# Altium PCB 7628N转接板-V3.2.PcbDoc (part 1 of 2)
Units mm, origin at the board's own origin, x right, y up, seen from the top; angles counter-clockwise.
Board outline 53 x 34 mm, 2 copper layers (Top, Bottom), stack 1.981 mm thick; 6 components, 131 nets, 219 pads, 60 vias.
Unrouted connection lines stored in the file: 5.
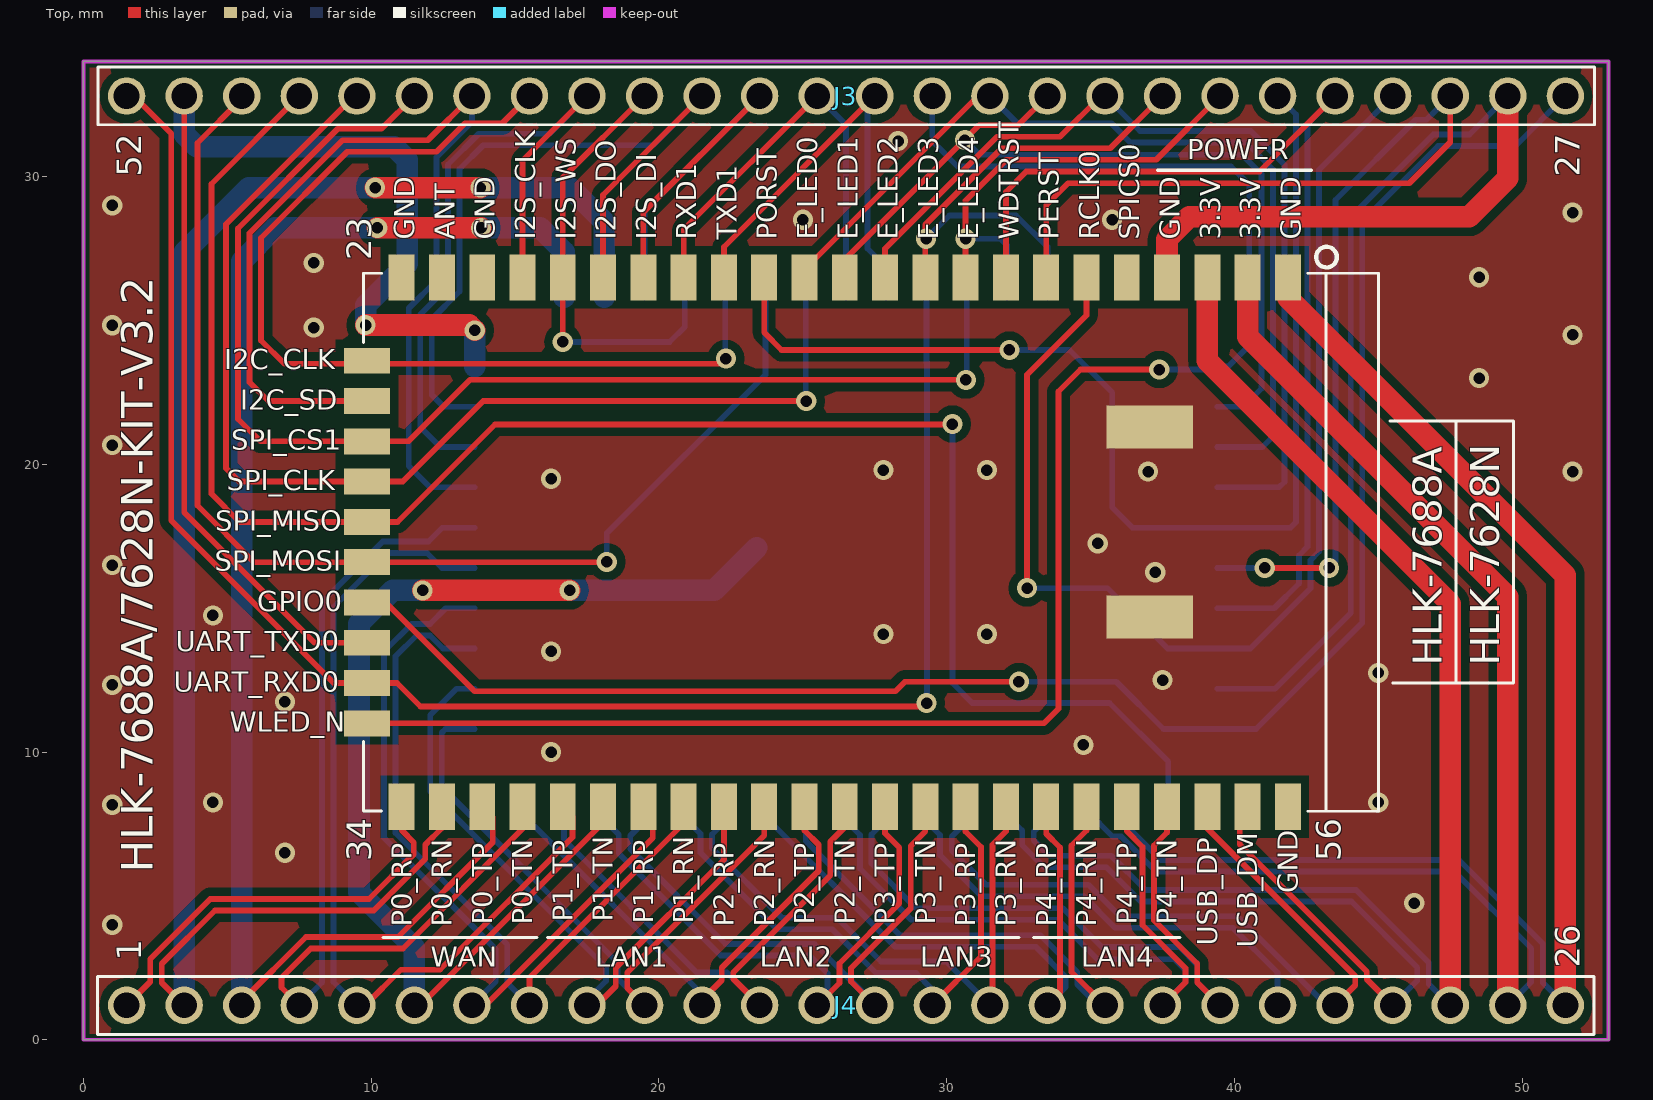
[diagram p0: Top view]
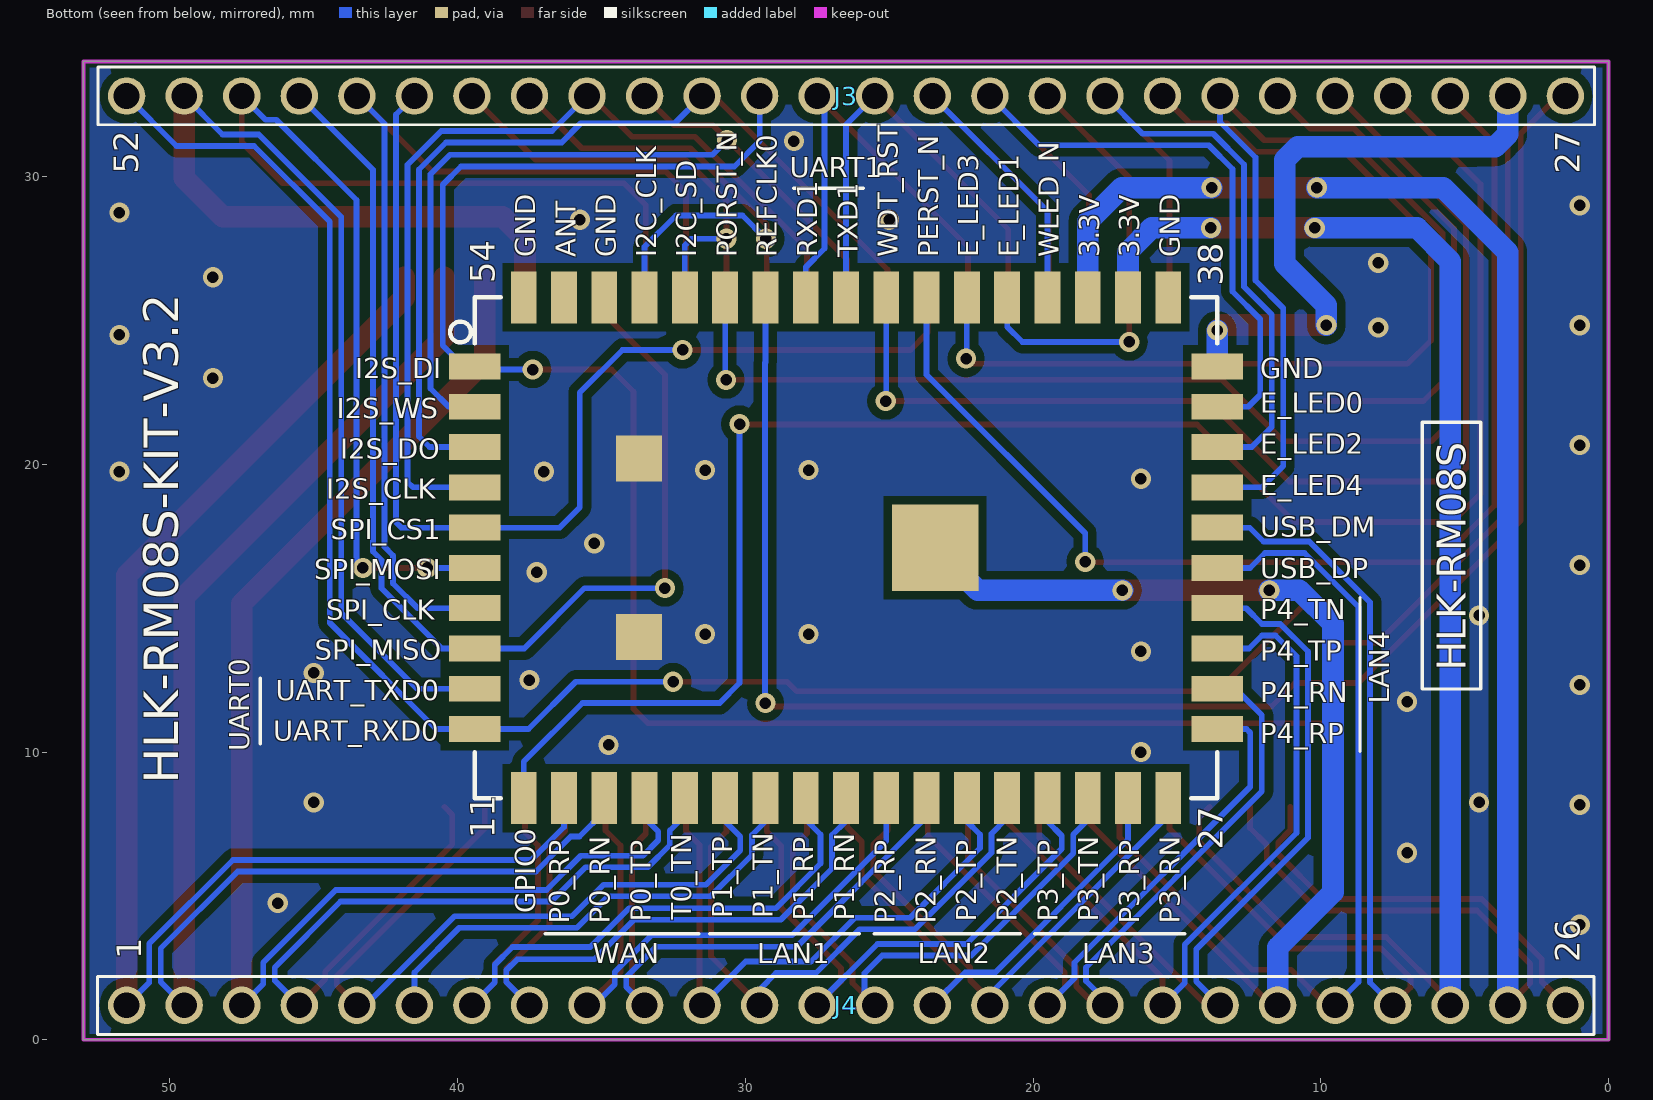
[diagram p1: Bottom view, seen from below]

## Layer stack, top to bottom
Solder Mask Top: solder mask 0.0102, Solder Resist, Dk 3.5
Top: signal copper 0.0178
Dielectric1: core 1.9456, FR-4, Dk 4.2
Bottom: signal copper 0.0178
Solder Mask Bottom: solder mask 0.0102, Solder Resist, Dk 3.5

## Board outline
0,0 53,0 53,34 0,34

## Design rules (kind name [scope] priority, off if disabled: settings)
Clearance [OnLayer('Keep-Out Layer')] p1: gap=0.15 ignorepadtopadclearanceinfootprint=FALSE
Clearance "'Net vs. Class' PADS rule_67" [All] p2: gap=0.3 ignorepadtopadclearanceinfootprint=FALSE
Clearance "'Net vs. Class' PADS rule_66" [InNet('GND') vs InNetClass('50OHM') And (IsTrack Or IsArc Or IsThruPin Or IsSMTPin Or IsVia Or IsFill Or InPolygon)] p3 off: gap=0.203 ignorepadtopadclearanceinfootprint=FALSE
Clearance "'Net vs. Class' PADS rule_64" [InNet('GND') vs InNetClass('DQ')] p4 off: gap=0.127 ignorepadtopadclearanceinfootprint=FALSE
Clearance "'Net vs. Class' PADS rule_63" [InNet('GND') And IsSMTPin vs InNetClass('DQ') And IsSMTPin] p5 off: gap=0.178 ignorepadtopadclearanceinfootprint=FALSE
Clearance "'Net vs. Class' PADS rule_62" [InNet('GND') vs InNetClass('DQ') And (IsTrack Or IsArc Or IsThruPin Or IsSMTPin Or IsVia Or IsFill Or InPolygon)] p6 off: gap=0.127 ignorepadtopadclearanceinfootprint=FALSE
Clearance "'Net vs. Class' PADS rule_60" [InNet('GND') vs InNetClass('90OHM')] p7 off: gap=0.203 ignorepadtopadclearanceinfootprint=FALSE
Clearance "'Net vs. Class' PADS rule_59" [InNet('GND') And IsSMTPin vs InNetClass('90OHM') And IsSMTPin] p8 off: gap=0.178 ignorepadtopadclearanceinfootprint=FALSE
Clearance "'Net vs. Class' PADS rule_58" [InNet('GND') vs InNetClass('90OHM') And (IsTrack Or IsArc Or IsThruPin Or IsSMTPin Or IsVia Or IsFill Or InPolygon)] p9 off: gap=0.203 ignorepadtopadclearanceinfootprint=FALSE
Clearance "'Net vs. Class' PADS rule_56" [InNet('GND') vs InNetClass('100OHM')] p10 off: gap=0.203 ignorepadtopadclearanceinfootprint=FALSE
Clearance "'Net vs. Class' PADS rule_54" [InNet('GND') vs InNetClass('100OHM') And (IsTrack Or IsArc Or IsThruPin Or IsSMTPin Or IsVia Or IsFill Or InPolygon)] p11 off: gap=0.203 ignorepadtopadclearanceinfootprint=FALSE
Clearance "'Net vs. Class' PADS rule_52" [InNet('GND') vs InNetClass('CA')] p12 off: gap=0.127 ignorepadtopadclearanceinfootprint=FALSE
Clearance "'Net vs. Class' PADS rule_51" [InNet('GND') And IsSMTPin vs InNetClass('CA') And IsSMTPin] p13 off: gap=0.178 ignorepadtopadclearanceinfootprint=FALSE
Clearance "'Net vs. Class' PADS rule_50" [InNet('GND') vs InNetClass('CA') And (IsTrack Or IsArc Or IsThruPin Or IsSMTPin Or IsVia Or IsFill Or InPolygon)] p14 off: gap=0.127 ignorepadtopadclearanceinfootprint=FALSE
Clearance "'Classon Layer' PADS rule_48" [InNetClass('DQ') And OnLayer('Top') And IsSMTPin vs IsSMTPin] p15 off: gap=0.178 ignorepadtopadclearanceinfootprint=FALSE
Clearance "'Classon Layer' PADS rule_47" [InNetClass('DQ') And OnLayer('Top') vs (IsTrack Or IsArc Or IsThruPin Or IsSMTPin Or IsVia Or IsFill Or InPolygon)] p16 off: gap=0.127 ignorepadtopadclearanceinfootprint=FALSE
Clearance "'Classon Layer' PADS rule_44" [InNetClass('CA') And OnLayer('Top') And IsSMTPin vs IsSMTPin] p17 off: gap=0.178 ignorepadtopadclearanceinfootprint=FALSE
Clearance "'Classon Layer' PADS rule_42" [InNetClass('CA') And OnLayer('Top') And (IsTrack Or IsArc) vs (IsTrack Or IsArc)] p18 off: gap=0.254 ignorepadtopadclearanceinfootprint=FALSE
Clearance "'Classon Layer' PADS rule_41" [InNetClass('CA') And OnLayer('Top') vs (IsTrack Or IsArc Or IsThruPin Or IsSMTPin Or IsVia Or IsFill Or InPolygon)] p19 off: gap=0.127 ignorepadtopadclearanceinfootprint=FALSE
Clearance "'Net' PADS rule_36" [InNetClass('Protel Created NetClass - 1') And (IsTrack Or IsArc) vs (IsTrack Or IsArc)] p20 off: gap=0.102 ignorepadtopadclearanceinfootprint=FALSE
Clearance "'Class' PADS rule_32" [InNetClass('100OHM') And IsSMTPin vs IsSMTPin] p21 off: gap=0.178 ignorepadtopadclearanceinfootprint=FALSE
Clearance "'Class' PADS rule_31" [InNetClass('100OHM') vs (IsTrack Or IsArc Or IsThruPin Or IsSMTPin Or IsVia Or IsFill Or InPolygon)] p22 off: gap=0.152 ignorepadtopadclearanceinfootprint=FALSE
Clearance "'Class' PADS rule_28" [InNetClass('90OHM') vs (IsTrack Or IsArc Or IsThruPin Or IsSMTPin Or IsVia Or IsFill Or InPolygon)] p23 off: gap=0.178 ignorepadtopadclearanceinfootprint=FALSE
Clearance "'Class' PADS rule_23" [InNetClass('50OHM') And IsSMTPin vs IsSMTPin] p24 off: gap=0.178 ignorepadtopadclearanceinfootprint=FALSE
Clearance "'Class' PADS rule_22" [InNetClass('50OHM') vs (IsTrack Or IsArc Or IsThruPin Or IsSMTPin Or IsVia Or IsFill Or InPolygon)] p25 off: gap=0.203 ignorepadtopadclearanceinfootprint=FALSE
Clearance "'Classon Layer' PADS rule_49" [InNetClass('DQ') And OnLayer('Top')] p26 off: gap=0.127 ignorepadtopadclearanceinfootprint=FALSE
Clearance "'Classon Layer' PADS rule_45" [InNetClass('CA') And OnLayer('Top')] p27 off: gap=0.127 ignorepadtopadclearanceinfootprint=FALSE
Clearance "'Classon Layer' PADS rule_43" [InNetClass('CA') And OnLayer('Top')] p28 off: gap=0.127 ignorepadtopadclearanceinfootprint=FALSE
Clearance "'Net' PADS rule_37" [InNetClass('Protel Created NetClass - 1')] p29 off: gap=0.102 ignorepadtopadclearanceinfootprint=FALSE
Clearance "'Class' PADS rule_33" [InNetClass('100OHM')] p30 off: gap=0.152 ignorepadtopadclearanceinfootprint=FALSE
Clearance "'Class' PADS rule_24" [InNetClass('50OHM')] p31 off: gap=0.203 ignorepadtopadclearanceinfootprint=FALSE
Clearance "'Default' PADS rule_19" [All] p32 off: gap=0.102 ignorepadtopadclearanceinfootprint=FALSE
Clearance "'Default' PADS rule_18" [IsSMTPin vs IsSMTPin] p33 off: gap=0.178 ignorepadtopadclearanceinfootprint=FALSE
Clearance "'Default' PADS rule_17" [All] p34 off: gap=0.102 ignorepadtopadclearanceinfootprint=FALSE
Clearance "'Default' PADS rule_16" [(IsTrack Or IsArc) vs (IsTrack Or IsArc)] p35 off: gap=0.127 ignorepadtopadclearanceinfootprint=FALSE
Clearance "'Default' PADS rule_15" [All] p36 off: gap=0.102 ignorepadtopadclearanceinfootprint=FALSE
ComponentClearance "'Default' PADS rule_12" [All] p1: gap=0 collisioncheckmode=3 verticalgap=0.254 showdistances=FALSE
FabricationTestpoint [(IsPad And (OnTopLayer Or OnBottomLayer))] p1: side=3 testpointundercomponent=TRUE minsize=1.016 maxsize=2.54 preferedsize=1.524 minholesize=0 maxholesize=1.016 preferedholesize=0.813 testpointgrid=0.025 allowsidetop=TRUE allowsidebottom=TRUE usegrid=TRUE gridtolerance=0
FlightTimeFalling "'Default' PADS rule_6" [All] p1: maximum=10.00
FlightTimeRising "'Default' PADS rule_5" [All] p1: maximum=10.00
Length "'Default' PADS rule" [All] p1: maxlimit=1270 minlimit=0
MatchedLengths "'Default' PADS rule_7" [InNetClass('All Nets')] p1: tolerance=5.08 checknetsindiffpair=TRUE checkdiffpairvsdiffpair=FALSE checkxsignals=FALSE checkothers=FALSE
MaxMinImpedance "'Default' PADS rule_4" [All] p1: minimum=50.00 maximum=150.0
ParallelSegment "'Default' PADS rule_3" [All] p1: limit=25.4 gap=5.08
ParallelSegment "'Default' PADS rule_2" [All] p2: limit=25.4 gap=5.08
PlaneClearance "'Net vs. Class' PADS rule_65" [InNet('GND') vs InNetClass('50OHM')] p1: clearance=0.203
PlaneClearance "'Net vs. Class' PADS rule_61" [InNet('GND') vs InNetClass('DQ')] p2: clearance=0.152
PlaneClearance "'Net vs. Class' PADS rule_57" [InNet('GND') vs InNetClass('90OHM')] p3: clearance=0.203
PlaneClearance "'Net vs. Class' PADS rule_53" [InNet('GND') vs InNetClass('100OHM')] p4: clearance=0.203
PlaneClearance "'Net vs. Class' PADS rule" [InNet('GND') vs InNetClass('CA')] p5: clearance=0.152
PlaneClearance "'Net' PADS rule_39" [InNetClass('Protel Created NetClass - 2')] p6: clearance=0.152
PlaneClearance "'Net' PADS rule_35" [InNetClass('Protel Created NetClass - 1')] p7: clearance=0.254
PlaneClearance "'Class' PADS rule_29" [InNetClass('100OHM')] p8: clearance=0.152
PlaneClearance "'Class' PADS rule_26" [InNetClass('90OHM')] p9: clearance=0.178
PlaneClearance "'Class' PADS rule_20" [InNetClass('50OHM')] p10: clearance=0.203
PlaneClearance "'Net' PADS rule" [InNetClass('Protel Created NetClass - 3')] p11: clearance=0.152
PlaneClearance "'Default' PADS rule_14" [All] p12: clearance=0.127
PlaneConnect "Power Plane Connect Style - Via from round thru-hole global defaults" [IsVia] p1: planeconnectstyle=Direct reliefexpansion=0.508 reliefentries=4 reliefconductorwidth=0.508 reliefairgap=0.254
PlaneConnect "Power Plane Connect Style - Round thru-hole pad from global defaults" [IsPad And OnMultiLayer And (PadShape_MidLayer1 = 'Round') And (PadXSize_MidLayer1 = PadYSize_MidLayer1)] p2: planeconnectstyle=Direct reliefexpansion=0.508 reliefentries=4 reliefconductorwidth=0.508 reliefairgap=0.254
PlaneConnect "Power Plane Connect Style - Square thru-hole pad from global defaults" [IsPad And OnMultiLayer And ((PadShape_MidLayer1 = 'Rectangular') Or (PadShape_MidLayer1 = 'Octagonal') Or (PadShape_MidLayer1 = 'Rounded Rectangle')) And (PadXSize_MidLayer1 = PadYSize_MidLayer1)] p3: planeconnectstyle=Direct reliefexpansion=0.508 reliefentries=4 reliefconductorwidth=0.508 reliefairgap=0.254
PlaneConnect "Power Plane Connect Style - Rect thru-hole pad from global defaults" [IsPad And OnMultiLayer And ((PadShape_MidLayer1 = 'Rectangular') Or (PadShape_MidLayer1 = 'Octagonal') Or (PadShape_MidLayer1 = 'Rounded Rectangle')) And (PadXSize_MidLayer1 <> PadYSize_MidLayer1)] p4: planeconnectstyle=Direct reliefexpansion=0.508 reliefentries=4 reliefconductorwidth=0.508 reliefairgap=0.254
PlaneConnect "Power Plane Connect Style - Square-rect thru-hole pad from global defaults" [IsPad And OnMultiLayer And (PadShape_MidLayer1 = 'Rounded Rectangle') And (PadXSize_MidLayer1 = PadYSize_MidLayer1) And (Pad_CornerRadius_MidLayer1 = '0%')] p5: planeconnectstyle=Direct reliefexpansion=0.508 reliefentries=4 reliefconductorwidth=0.508 reliefairgap=0.254
PlaneConnect "Power Plane Connect Style - Oval thru-hole pad from global defaults" [IsPad And OnMultiLayer And (PadShape_MidLayer1 = 'Round') And (PadXSize_MidLayer1 <> PadYSize_MidLayer1)] p6: planeconnectstyle=Relief reliefexpansion=0.508 reliefentries=4 reliefconductorwidth=0.508 reliefairgap=0.254
PlaneConnect "Power Plane Connect Style - Round-oval thru-hole pad from global defaults" [IsPad And OnMultiLayer And (PadShape_MidLayer1 = 'Rounded Rectangle') And (PadXSize_MidLayer1 = PadYSize_MidLayer1) And (Pad_CornerRadius_MidLayer1 = '100%')] p7: planeconnectstyle=Relief reliefexpansion=0.508 reliefentries=4 reliefconductorwidth=0.508 reliefairgap=0.254
PolygonConnect "Polygon Connect Style - Bottom Round SMD from global defaults" [IsSMTPin And (PadShape_BottomLayer = 'Round') And (PadXSize_BottomLayer = PADYSize_BottomLayer) vs Layer = 'Bottom'] p1: connectstyle=Direct reliefconductorwidth=0.203 reliefentries=4 polygonreliefangle="45 Angle" airgapwidth=0.254
PolygonConnect "Polygon Connect Style - Top Round SMD from global defaults" [IsSMTPin And (PadShape_TopLayer = 'Round') And (PadXSize_TopLayer = PADYSize_TopLayer) vs Layer = 'Top'] p2: connectstyle=Direct reliefconductorwidth=0.203 reliefentries=4 polygonreliefangle="45 Angle" airgapwidth=0.254
PolygonConnect "Polygon Connect Style - Bottom Square SMD from global defaults 1" [IsSMTPin And (PadShape_BottomLayer = 'Rectangular') And (PadXSize_BottomLayer = PADYSize_BottomLayer) vs Layer = 'Bottom'] p3: connectstyle=Direct reliefconductorwidth=0.203 reliefentries=4 polygonreliefangle="45 Angle" airgapwidth=0.254
PolygonConnect "Polygon Connect Style - Bottom Square SMD from global defaults 2" [IsSMTPin And (PadShape_BottomLayer = 'Octagonal') And (PadXSize_BottomLayer = PADYSize_BottomLayer) vs Layer = 'Bottom'] p4: connectstyle=Direct reliefconductorwidth=0.203 reliefentries=4 polygonreliefangle="45 Angle" airgapwidth=0.254
PolygonConnect "Polygon Connect Style - Bottom Square SMD from global defaults 3" [IsSMTPin And (PadShape_BottomLayer = 'Rounded Rectangle') And (PadXSize_BottomLayer = PADYSize_BottomLayer) vs Layer = 'Bottom'] p5: connectstyle=Direct reliefconductorwidth=0.203 reliefentries=4 polygonreliefangle="45 Angle" airgapwidth=0.254
PolygonConnect "Polygon Connect Style - Top Square SMD from global defaults 1" [IsSMTPin And (PadShape_TopLayer = 'Rectangular') And (PadXSize_TopLayer = PADYSize_TopLayer) vs Layer = 'Top'] p6: connectstyle=Direct reliefconductorwidth=0.203 reliefentries=4 polygonreliefangle="45 Angle" airgapwidth=0.254
PolygonConnect "Polygon Connect Style - Top Square SMD from global defaults 2" [IsSMTPin And (PadShape_TopLayer = 'Octagonal') And (PadXSize_TopLayer = PADYSize_TopLayer) vs Layer = 'Top'] p7: connectstyle=Direct reliefconductorwidth=0.203 reliefentries=4 polygonreliefangle="45 Angle" airgapwidth=0.254
PolygonConnect "Polygon Connect Style - Top Square SMD from global defaults 3" [IsSMTPin And (PadShape_TopLayer = 'Rounded Rectangle') And (PadXSize_TopLayer = PADYSize_TopLayer) vs Layer = 'Top'] p8: connectstyle=Direct reliefconductorwidth=0.203 reliefentries=4 polygonreliefangle="45 Angle" airgapwidth=0.254
PolygonConnect "Polygon Connect Style - Bottom Rect SMD from global defaults 1" [IsSMTPin And (PadShape_BottomLayer = 'Rectangular') And (PadXSize_BottomLayer <> PADYSize_BottomLayer) vs Layer = 'Bottom'] p9: connectstyle=Direct reliefconductorwidth=0.203 reliefentries=4 polygonreliefangle="45 Angle" airgapwidth=0.254
PolygonConnect "Polygon Connect Style - Bottom Rect SMD from global defaults 2" [IsSMTPin And (PadShape_BottomLayer = 'Octagonal') And (PadXSize_BottomLayer <> PADYSize_BottomLayer) vs Layer = 'Bottom'] p10: connectstyle=Direct reliefconductorwidth=0.203 reliefentries=4 polygonreliefangle="45 Angle" airgapwidth=0.254
PolygonConnect "Polygon Connect Style - Bottom Rect SMD from global defaults 3" [IsSMTPin And (PadShape_BottomLayer = 'Rounded Rectangle') And (PadXSize_BottomLayer <> PADYSize_BottomLayer) vs Layer = 'Bottom'] p11: connectstyle=Direct reliefconductorwidth=0.203 reliefentries=4 polygonreliefangle="45 Angle" airgapwidth=0.254
PolygonConnect "Polygon Connect Style - Bottom Square-rect SMD pad from global defaults" [IsSMTPin And (PadShape_BottomLayer = 'Rounded Rectangle') And (PadXSize_BottomLayer = PADYSize_BottomLayer) And (Pad_CornerRadius_BottomLayer = '0%') vs Layer = 'Bottom'] p12: connectstyle=Direct reliefconductorwidth=0.203 reliefentries=4 polygonreliefangle="45 Angle" airgapwidth=0.254
PolygonConnect "Polygon Connect Style - Top Rect SMD from global defaults 1" [IsSMTPin And (PadShape_TopLayer = 'Rectangular') And (PadXSize_TopLayer <> PADYSize_TopLayer) vs Layer = 'Top'] p13: connectstyle=Direct reliefconductorwidth=0.203 reliefentries=4 polygonreliefangle="45 Angle" airgapwidth=0.254
PolygonConnect "Polygon Connect Style - Top Rect SMD from global defaults 2" [IsSMTPin And (PadShape_TopLayer = 'Octagonal') And (PadXSize_TopLayer <> PADYSize_TopLayer) vs Layer = 'Top'] p14: connectstyle=Direct reliefconductorwidth=0.203 reliefentries=4 polygonreliefangle="45 Angle" airgapwidth=0.254
PolygonConnect "Polygon Connect Style - Top Rect SMD from global defaults 3" [IsSMTPin And (PadShape_TopLayer = 'Rounded Rectangle') And (PadXSize_TopLayer <> PADYSize_TopLayer) vs Layer = 'Top'] p15: connectstyle=Direct reliefconductorwidth=0.203 reliefentries=4 polygonreliefangle="45 Angle" airgapwidth=0.254
PolygonConnect "Polygon Connect Style - Top Square-rect SMD pad from global defaults" [IsSMTPin And (PadShape_TopLayer = 'Rounded Rectangle') And (PadXSize_TopLayer = PADYSize_TopLayer) And (Pad_CornerRadius_TopLayer = '0%') vs Layer = 'Top'] p16: connectstyle=Direct reliefconductorwidth=0.203 reliefentries=4 polygonreliefangle="45 Angle" airgapwidth=0.254
PolygonConnect "Polygon Connect Style - Bottom Oval SMD from global defaults" [IsSMTPin And (PadShape_BottomLayer = 'Round') And (PadXSize_BottomLayer <> PADYSize_BottomLayer) vs Layer = 'Bottom'] p17: connectstyle=Direct reliefconductorwidth=0.203 reliefentries=4 polygonreliefangle="45 Angle" airgapwidth=0.254
PolygonConnect "Polygon Connect Style - Bottom Round-oval SMD pad from global defaults" [IsSMTPin And (PadShape_BottomLayer = 'Rounded Rectangle') And (PadXSize_BottomLayer = PADYSize_BottomLayer) And (Pad_CornerRadius_BottomLayer = '100%') vs Layer = 'Bottom'] p18: connectstyle=Direct reliefconductorwidth=0.203 reliefentries=4 polygonreliefangle="45 Angle" airgapwidth=0.254
PolygonConnect "Polygon Connect Style - Top Oval SMD from global defaults" [IsSMTPin And (PadShape_TopLayer = 'Round') And (PadXSize_TopLayer <> PADYSize_TopLayer) vs Layer = 'Top'] p19: connectstyle=Direct reliefconductorwidth=0.203 reliefentries=4 polygonreliefangle="45 Angle" airgapwidth=0.254
PolygonConnect "Polygon Connect Style - Top Round-oval SMD pad from global defaults" [IsSMTPin And (PadShape_TopLayer = 'Rounded Rectangle') And (PadXSize_TopLayer = PADYSize_TopLayer) And (Pad_CornerRadius_TopLayer = '100%') vs Layer = 'Top'] p20: connectstyle=Direct reliefconductorwidth=0.203 reliefentries=4 polygonreliefangle="45 Angle" airgapwidth=0.254
PolygonConnect "Polygon Connect Style - Via from round thru-hole global defaults_71" [IsVia] p21: connectstyle=Direct reliefconductorwidth=0.508 reliefentries=4 polygonreliefangle="45 Angle" airgapwidth=0.254
PolygonConnect "Polygon Connect Style - Bottom Round thru-hole pad from global defaults" [IsPad And OnMultiLayer And (PadShape_BottomLayer = 'Round') And (PadXSize_BottomLayer = PADYSize_BottomLayer) vs Layer = 'Bottom'] p22: connectstyle=Direct reliefconductorwidth=0.508 reliefentries=4 polygonreliefangle="45 Angle" airgapwidth=0.254
PolygonConnect "Polygon Connect Style - Via from round thru-hole global defaults_70" [IsVia] p23: connectstyle=Direct reliefconductorwidth=0.508 reliefentries=4 polygonreliefangle="45 Angle" airgapwidth=0.254
PolygonConnect "Polygon Connect Style - Inner Layer 3 Round thru-hole pad from global defaults" [IsPad And OnMultiLayer And (PadShape_MidLayer2 = 'Round') And (PadXSize_MidLayer2 = PADYSize_MidLayer2) vs Layer = 'Inner Layer 3'] p24: connectstyle=Direct reliefconductorwidth=0.508 reliefentries=4 polygonreliefangle="45 Angle" airgapwidth=0.254
PolygonConnect "Polygon Connect Style - Via from round thru-hole global defaults_69" [IsVia] p25: connectstyle=Direct reliefconductorwidth=0.508 reliefentries=4 polygonreliefangle="45 Angle" airgapwidth=0.254
PolygonConnect "Polygon Connect Style - Inner Layer 2 Round thru-hole pad from global defaults" [IsPad And OnMultiLayer And (PadShape_MidLayer1 = 'Round') And (PadXSize_MidLayer1 = PADYSize_MidLayer1) vs Layer = 'Inner Layer 2'] p26: connectstyle=Direct reliefconductorwidth=0.508 reliefentries=4 polygonreliefangle="45 Angle" airgapwidth=0.254
PolygonConnect "Polygon Connect Style - Via from round thru-hole global defaults" [IsVia] p27: connectstyle=Direct reliefconductorwidth=0.508 reliefentries=4 polygonreliefangle="45 Angle" airgapwidth=0.254
PolygonConnect "Polygon Connect Style - Top Round thru-hole pad from global defaults" [IsPad And OnMultiLayer And (PadShape_TopLayer = 'Round') And (PadXSize_TopLayer = PADYSize_TopLayer) vs Layer = 'Top'] p28: connectstyle=Direct reliefconductorwidth=0.508 reliefentries=4 polygonreliefangle="45 Angle" airgapwidth=0.254
PolygonConnect "Polygon Connect Style - Bottom Square thru-hole pad from global defaults" [IsPad And OnMultiLayer And ((PadShape_BottomLayer = 'Rectangular') Or (PadShape_BottomLayer = 'Octagonal') Or (PadShape_BottomLayer = 'Rounded Rectangle')) And (PadXSize_BottomLayer = PADYSize_BottomLayer) vs Layer = 'Bottom'] p29: connectstyle=Direct reliefconductorwidth=0.508 reliefentries=4 polygonreliefangle="45 Angle" airgapwidth=0.254
PolygonConnect "Polygon Connect Style - Inner Layer 3 Square thru-hole pad from global defaults" [IsPad And OnMultiLayer And ((PadShape_MidLayer2 = 'Rectangular') Or (PadShape_MidLayer2 = 'Octagonal') Or (PadShape_MidLayer2 = 'Rounded Rectangle')) And (PadXSize_MidLayer2 = PADYSize_MidLayer2) vs Layer = 'Inner Layer 3'] p30: connectstyle=Direct reliefconductorwidth=0.508 reliefentries=4 polygonreliefangle="45 Angle" airgapwidth=0.254
PolygonConnect "Polygon Connect Style - Inner Layer 2 Square thru-hole pad from global defaults" [IsPad And OnMultiLayer And ((PadShape_MidLayer1 = 'Rectangular') Or (PadShape_MidLayer1 = 'Octagonal') Or (PadShape_MidLayer1 = 'Rounded Rectangle')) And (PadXSize_MidLayer1 = PADYSize_MidLayer1) vs Layer = 'Inner Layer 2'] p31: connectstyle=Direct reliefconductorwidth=0.508 reliefentries=4 polygonreliefangle="45 Angle" airgapwidth=0.254
PolygonConnect "Polygon Connect Style - Top Square thru-hole pad from global defaults" [IsPad And OnMultiLayer And ((PadShape_TopLayer = 'Rectangular') Or (PadShape_TopLayer = 'Octagonal') Or (PadShape_TopLayer = 'Rounded Rectangle')) And (PadXSize_TopLayer = PADYSize_TopLayer) vs Layer = 'Top'] p32: connectstyle=Direct reliefconductorwidth=0.508 reliefentries=4 polygonreliefangle="45 Angle" airgapwidth=0.254
PolygonConnect "Polygon Connect Style - Bottom Rect thru-hole pad from global defaults" [IsPad And OnMultiLayer And ((PadShape_BottomLayer = 'Rectangular') Or (PadShape_BottomLayer = 'Octagonal') Or (PadShape_BottomLayer = 'Rounded Rectangle')) And (PadXSize_BottomLayer <> PADYSize_BottomLayer) vs Layer = 'Bottom'] p33: connectstyle=Direct reliefconductorwidth=0.508 reliefentries=4 polygonreliefangle="45 Angle" airgapwidth=0.254
PolygonConnect "Polygon Connect Style - Bottom Square-rect thru-hole pad from global defaults" [IsPad And OnMultiLayer And (PadShape_BottomLayer = 'Rounded Rectangle') And (PadXSize_BottomLayer = PADYSize_BottomLayer) And (Pad_CornerRadius_BottomLayer = '0%') vs Layer = 'Bottom'] p34: connectstyle=Direct reliefconductorwidth=0.508 reliefentries=4 polygonreliefangle="45 Angle" airgapwidth=0.254
PolygonConnect "Polygon Connect Style - Inner Layer 3 Rect thru-hole pad from global defaults" [IsPad And OnMultiLayer And ((PadShape_MidLayer2 = 'Rectangular') Or (PadShape_MidLayer2 = 'Octagonal') Or (PadShape_MidLayer2 = 'Rounded Rectangle')) And (PadXSize_MidLayer2 <> PADYSize_MidLayer2) vs Layer = 'Inner Layer 3'] p35: connectstyle=Direct reliefconductorwidth=0.508 reliefentries=4 polygonreliefangle="45 Angle" airgapwidth=0.254
PolygonConnect "Polygon Connect Style - Inner Layer 3 Square-rect thru-hole pad from global defaults" [IsPad And OnMultiLayer And (PadShape_MidLayer2 = 'Rounded Rectangle') And (PadXSize_MidLayer2 = PADYSize_MidLayer2) And (Pad_CornerRadius_MidLayer2 = '0%') vs Layer = 'Inner Layer 3'] p36: connectstyle=Direct reliefconductorwidth=0.508 reliefentries=4 polygonreliefangle="45 Angle" airgapwidth=0.254
PolygonConnect "Polygon Connect Style - Inner Layer 2 Rect thru-hole pad from global defaults" [IsPad And OnMultiLayer And ((PadShape_MidLayer1 = 'Rectangular') Or (PadShape_MidLayer1 = 'Octagonal') Or (PadShape_MidLayer1 = 'Rounded Rectangle')) And (PadXSize_MidLayer1 <> PADYSize_MidLayer1) vs Layer = 'Inner Layer 2'] p37: connectstyle=Direct reliefconductorwidth=0.508 reliefentries=4 polygonreliefangle="45 Angle" airgapwidth=0.254
PolygonConnect "Polygon Connect Style - Inner Layer 2 Square-rect thru-hole pad from global defaults" [IsPad And OnMultiLayer And (PadShape_MidLayer1 = 'Rounded Rectangle') And (PadXSize_MidLayer1 = PADYSize_MidLayer1) And (Pad_CornerRadius_MidLayer1 = '0%') vs Layer = 'Inner Layer 2'] p38: connectstyle=Direct reliefconductorwidth=0.508 reliefentries=4 polygonreliefangle="45 Angle" airgapwidth=0.254
PolygonConnect "Polygon Connect Style - Top Rect thru-hole pad from global defaults" [IsPad And OnMultiLayer And ((PadShape_TopLayer = 'Rectangular') Or (PadShape_TopLayer = 'Octagonal') Or (PadShape_TopLayer = 'Rounded Rectangle')) And (PadXSize_TopLayer <> PADYSize_TopLayer) vs Layer = 'Top'] p39: connectstyle=Direct reliefconductorwidth=0.508 reliefentries=4 polygonreliefangle="45 Angle" airgapwidth=0.254
PolygonConnect "Polygon Connect Style - Top Square-rect thru-hole pad from global defaults" [IsPad And OnMultiLayer And (PadShape_TopLayer = 'Rounded Rectangle') And (PadXSize_TopLayer = PADYSize_TopLayer) And (Pad_CornerRadius_TopLayer = '0%') vs Layer = 'Top'] p40: connectstyle=Direct reliefconductorwidth=0.508 reliefentries=4 polygonreliefangle="45 Angle" airgapwidth=0.254
PolygonConnect "Polygon Connect Style - Bottom Oval thru-hole pad from global defaults" [IsPad And OnMultiLayer And (PadShape_BottomLayer = 'Round') And (PadXSize_BottomLayer <> PADYSize_BottomLayer) vs Layer = 'Bottom'] p41: connectstyle=Relief reliefconductorwidth=0.508 reliefentries=4 polygonreliefangle="45 Angle" airgapwidth=0.254
PolygonConnect "Polygon Connect Style - Bottom Round-oval thru-hole pad from global defaults" [IsPad And OnMultiLayer And (PadShape_BottomLayer = 'Rounded Rectangle') And (PadXSize_BottomLayer = PADYSize_BottomLayer) And (Pad_CornerRadius_BottomLayer = '100%') vs Layer = 'Bottom'] p42: connectstyle=Relief reliefconductorwidth=0.508 reliefentries=4 polygonreliefangle="45 Angle" airgapwidth=0.254
PolygonConnect "Polygon Connect Style - Inner Layer 3 Oval thru-hole pad from global defaults" [IsPad And OnMultiLayer And (PadShape_MidLayer2 = 'Round') And (PadXSize_MidLayer2 <> PADYSize_MidLayer2) vs Layer = 'Inner Layer 3'] p43: connectstyle=Relief reliefconductorwidth=0.508 reliefentries=4 polygonreliefangle="45 Angle" airgapwidth=0.254
PolygonConnect "Polygon Connect Style - Inner Layer 3 Round-oval thru-hole pad from global defaults" [IsPad And OnMultiLayer And (PadShape_MidLayer2 = 'Rounded Rectangle') And (PadXSize_MidLayer2 = PADYSize_MidLayer2) And (Pad_CornerRadius_MidLayer2 = '100%') vs Layer = 'Inner Layer 3'] p44: connectstyle=Relief reliefconductorwidth=0.508 reliefentries=4 polygonreliefangle="45 Angle" airgapwidth=0.254
PolygonConnect "Polygon Connect Style - Inner Layer 2 Oval thru-hole pad from global defaults" [IsPad And OnMultiLayer And (PadShape_MidLayer1 = 'Round') And (PadXSize_MidLayer1 <> PADYSize_MidLayer1) vs Layer = 'Inner Layer 2'] p45: connectstyle=Relief reliefconductorwidth=0.508 reliefentries=4 polygonreliefangle="45 Angle" airgapwidth=0.254
PolygonConnect "Polygon Connect Style - Inner Layer 2 Round-oval thru-hole pad from global defaults" [IsPad And OnMultiLayer And (PadShape_MidLayer1 = 'Rounded Rectangle') And (PadXSize_MidLayer1 = PADYSize_MidLayer1) And (Pad_CornerRadius_MidLayer1 = '100%') vs Layer = 'Inner Layer 2'] p46: connectstyle=Relief reliefconductorwidth=0.508 reliefentries=4 polygonreliefangle="45 Angle" airgapwidth=0.254
PolygonConnect "Polygon Connect Style - Top Oval thru-hole pad from global defaults" [IsPad And OnMultiLayer And (PadShape_TopLayer = 'Round') And (PadXSize_TopLayer <> PADYSize_TopLayer) vs Layer = 'Top'] p47: connectstyle=Relief reliefconductorwidth=0.508 reliefentries=4 polygonreliefangle="45 Angle" airgapwidth=0.254
PolygonConnect "Polygon Connect Style - Top Round-oval thru-hole pad from global defaults" [IsPad And OnMultiLayer And (PadShape_TopLayer = 'Rounded Rectangle') And (PadXSize_TopLayer = PADYSize_TopLayer) And (Pad_CornerRadius_TopLayer = '100%') vs Layer = 'Top'] p48: connectstyle=Relief reliefconductorwidth=0.508 reliefentries=4 polygonreliefangle="45 Angle" airgapwidth=0.254
PolygonConnect [All] p49: connectstyle=Relief reliefconductorwidth=0.254 reliefentries=4 polygonreliefangle="90 Angle" airgapwidth=0.254
RoutingLayers "'Default' PADS rule_10" [All] p1: top layer_v5=TRUE bottom layer_v5=TRUE
RoutingPriority "'Default' PADS rule_9" [All] p1: routingpriority=3
RoutingTopology "'Default' PADS rule_8" [All] p1: topology=Shortest
RoutingVias "'Default' PADS rule_11" [All] p1: holewidth=0.4 width=0.7 viastyle="Through Hole" minholewidth=0.305 minwidth=0.7 maxholewidth=1 maxwidth=1
SMDToPlane "'Classon Layer' PADS rule_46" [InNetClass('DQ') And OnLayer('Top')] p1: distance=20000
SMDToPlane "'Classon Layer' PADS rule_40" [InNetClass('CA') And OnLayer('Top')] p2: distance=20000
SMDToPlane "'Class' PADS rule_30" [InNetClass('100OHM')] p3: distance=20000
SMDToPlane "'Class' PADS rule_27" [InNetClass('90OHM')] p4: distance=20000
SMDToPlane "'Class' PADS rule_21" [InNetClass('50OHM')] p5: distance=20000
SolderMaskExpansion "Solder Mask Expansion from CAM settings" [All] p1: expansion=0.051 istentingtop=FALSE
Width "'Classon Layer' PADS rule" [InNetClass('CA') And OnLayer('Top')] p1 off: maxlimit=5.08 minlimit=0.127 preferedwidth=0.127
Width "'Net' PADS rule_38" [InNetClass('Protel Created NetClass - 2')] p2 off: maxlimit=5.08 minlimit=0.076 preferedwidth=0.165
Width "'Net' PADS rule_34" [InNetClass('Protel Created NetClass - 1')] p3 off: maxlimit=5.08 minlimit=0.076 preferedwidth=0.305
Width "'Class' PADS rule_25" [InNetClass('90OHM')] p4 off: maxlimit=5.08 minlimit=0.076 preferedwidth=0.178
Width "'Class' PADS rule" [InNetClass('50OHM')] p5 off: maxlimit=5.08 minlimit=0.076 preferedwidth=0.178
Width "'Default' PADS rule_13" [All] p6: maxlimit=2 minlimit=0.2 preferedwidth=0.2
23 further rules are at their usual default settings.

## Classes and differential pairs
net class CA: DDR_BA0 DDR_BA1 DDR_BA2 DDR_CASN DDR_CSN DDR_MCKE DDR_MODT DDR_RASN DDR_WEN MADDR0 MADDR1 MADDR2 MADDR3 MADDR4 MADDR5 MADDR6 MADDR7 MADDR8 MADDR9 MADDR10 MADDR11 MADDR12 MADDR13
net class CLASS_0: N17083158 N17083162 N17083174 N17083274 N17083406 N17083412 N17415955 N17415957 N17416113 N17416117 N17416125 N17416142 N17416414 RFOUT_G0_L WF0_IPA WF1_IPA
net class CLASS_1: RXIN0 RXIP0
net class CLASS_2: N18021801 N18021821 USB_DN USB_DP
net class DQ: DDR_MDQM0 DDR_MDQM1 DDR_MDQS0 DDR_MDQS1 MDATA0 MDATA1 MDATA2 MDATA3 MDATA4 MDATA5 MDATA6 MDATA7 MDATA8 MDATA9 MDATA10 MDATA11 MDATA12 MDATA13 MDATA14 MDATA15
net class "Protel Created NetClass - 1": N17083158 N17083162 N17083174 N17083274 N17083406 N17083412 N17415955 N17415957 N17416113 N17416117 N17416125 N17416142 N17416414 RFOUT_G0_L WF0_IPA WF1_IPA
net class "Protel Created NetClass - 2": N18021801 N18021821 USB_DN USB_DP
net class "Protel Created NetClass - 3": RXIN0 RXIP0

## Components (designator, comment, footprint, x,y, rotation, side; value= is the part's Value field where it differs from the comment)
HLK-7688A "Comment" 7688A 41.857,26.499 r0 top
HLK-RM08S "Comment" RM08S 39.4,8.4 r180 bottom locked
J3 "DIP-2.0-26P" DIP-2.0-26P 51.5,32.8 r180 bottom
J3 "DIP-2.0-26P" DIP-2.0-26P 1.5,32.8 r0 top
J4 "DIP-2.0-26P" DIP-2.0-26P 51.5,1.2 r180 bottom
J4 "DIP-2.0-26P" DIP-2.0-26P 1.5,1.2 r0 top

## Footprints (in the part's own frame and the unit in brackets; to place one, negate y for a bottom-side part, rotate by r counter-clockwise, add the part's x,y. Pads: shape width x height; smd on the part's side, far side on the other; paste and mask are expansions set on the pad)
7688A [mm]
  rect 0.9x1.6 smd: 1(0,0) 2(-1.4,0) 3(-2.8,0) 4(-4.2,0) 5(-5.6,0) 6(-7,0) 7(-8.4,0) 8(-9.8,0) 9(-11.2,0) 10(-12.6,0) 11(-14,0) 12(-15.4,0) 13(-16.8,0) 14(-18.2,0) 15(-19.6,0) 16(-21,0) 17(-22.4,0) 18(-23.8,0) 19(-25.2,0) 20(-26.6,0) 21(-28,0) 22(-29.4,0) 23(-30.8,0) 34(-30.8,-18.4) 35(-29.4,-18.4) 36(-28,-18.4) 37(-26.6,-18.4) 38(-25.2,-18.4) 39(-23.8,-18.4) 40(-22.4,-18.4) 41(-21,-18.4) 42(-19.6,-18.4) 43(-18.2,-18.4) 44(-16.8,-18.4) 45(-15.4,-18.4) 46(-14,-18.4) 47(-12.6,-18.4) 48(-11.2,-18.4) 49(-9.8,-18.4) 50(-8.4,-18.4) 51(-7,-18.4) 52(-5.6,-18.4) 53(-4.2,-18.4) 54(-2.8,-18.4) 55(-1.4,-18.4) 56(0,-18.4)
  rect 1.6x0.9 smd: 24(-32,-2.9) 25(-32,-4.3) 26(-32,-5.7) 27(-32,-7.1) 28(-32,-8.5) 29(-32,-9.9) 30(-32,-11.3) 31(-32,-12.7) 32(-32,-14.1) 33(-32,-15.5)
  rect 3x1.5 smd: 57(-4.8,-11.8) 58(-4.8,-5.2)
  silkscreen extent -32.13,-18.56 1.7,1.06
DIP-2.0-26P [mm]
  round 1.3 / inner round 1.2 / far side round 1.2 hole 0.9: 1(0,0) 2(2,0) 3(4,0) 4(6,0) 5(8,0) 6(10,0) 7(12,0) 8(14,0) 9(16,0) 10(18,0) 11(20,0) 12(22,0) 13(24,0) 14(26,0) 15(28,0) 16(30,0) 17(32,0) 18(34,0) 19(36,0) 20(38,0) 21(40,0) 22(42,0) 23(44,0) 24(46,0) 25(48,0) 26(50,0)
RM08S [mm]
  rect 1.8x0.9 smd: 1(0,15) 2(0,13.6) 3(0,12.2) 4(0,10.8) 5(0,9.4) 6(0,8) 7(0,6.6) 8(0,5.2) 9(0,3.8) 10(0,2.4) 28(25.8,2.4) 29(25.8,3.8) 30(25.8,5.2) 31(25.8,6.6) 32(25.8,8) 33(25.8,9.4) 34(25.8,10.8) 35(25.8,12.2) 36(25.8,13.6) 37(25.8,15)
  rect 0.9x1.8 smd: 11(1.7,0) 12(3.1,0) 13(4.5,0) 14(5.9,0) 15(7.3,0) 16(8.7,0) 17(10.1,0) 18(11.5,0) 19(12.9,0) 20(14.3,0) 21(15.7,0) 22(17.1,0) 23(18.5,0) 24(19.9,0) 25(21.3,0) 26(22.7,0) 27(24.1,0) 38(24.1,17.4) 39(22.7,17.4) 40(21.3,17.4) 41(19.9,17.4) 42(18.5,17.4) 43(17.1,17.4) 44(15.7,17.4) 45(14.3,17.4) 46(12.9,17.4) 47(11.5,17.4) 48(10.1,17.4) 49(8.7,17.4) 50(7.3,17.4) 51(5.9,17.4) 52(4.5,17.4) 53(3.1,17.4) 54(1.7,17.4)
  rect 1.6x1.6 smd: 55(5.7,11.8) 56(5.7,5.6)
  rect 3x3 smd: 57(16,8.7)
  silkscreen extent -0.86,0 25.8,17.4

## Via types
v1: diameter 0.7, hole 0.4, Top to Bottom, tented both sides, 59 vias
v2: diameter 0.7, hole 0.4, Top to Bottom, 1 vias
